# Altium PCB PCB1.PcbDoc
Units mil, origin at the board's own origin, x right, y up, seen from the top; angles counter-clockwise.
Board outline 3797.64 x 3149.61 mil, 2 copper layers (Top Layer, Bottom Layer); 74 components, 106 nets, 398 pads, 67 vias.
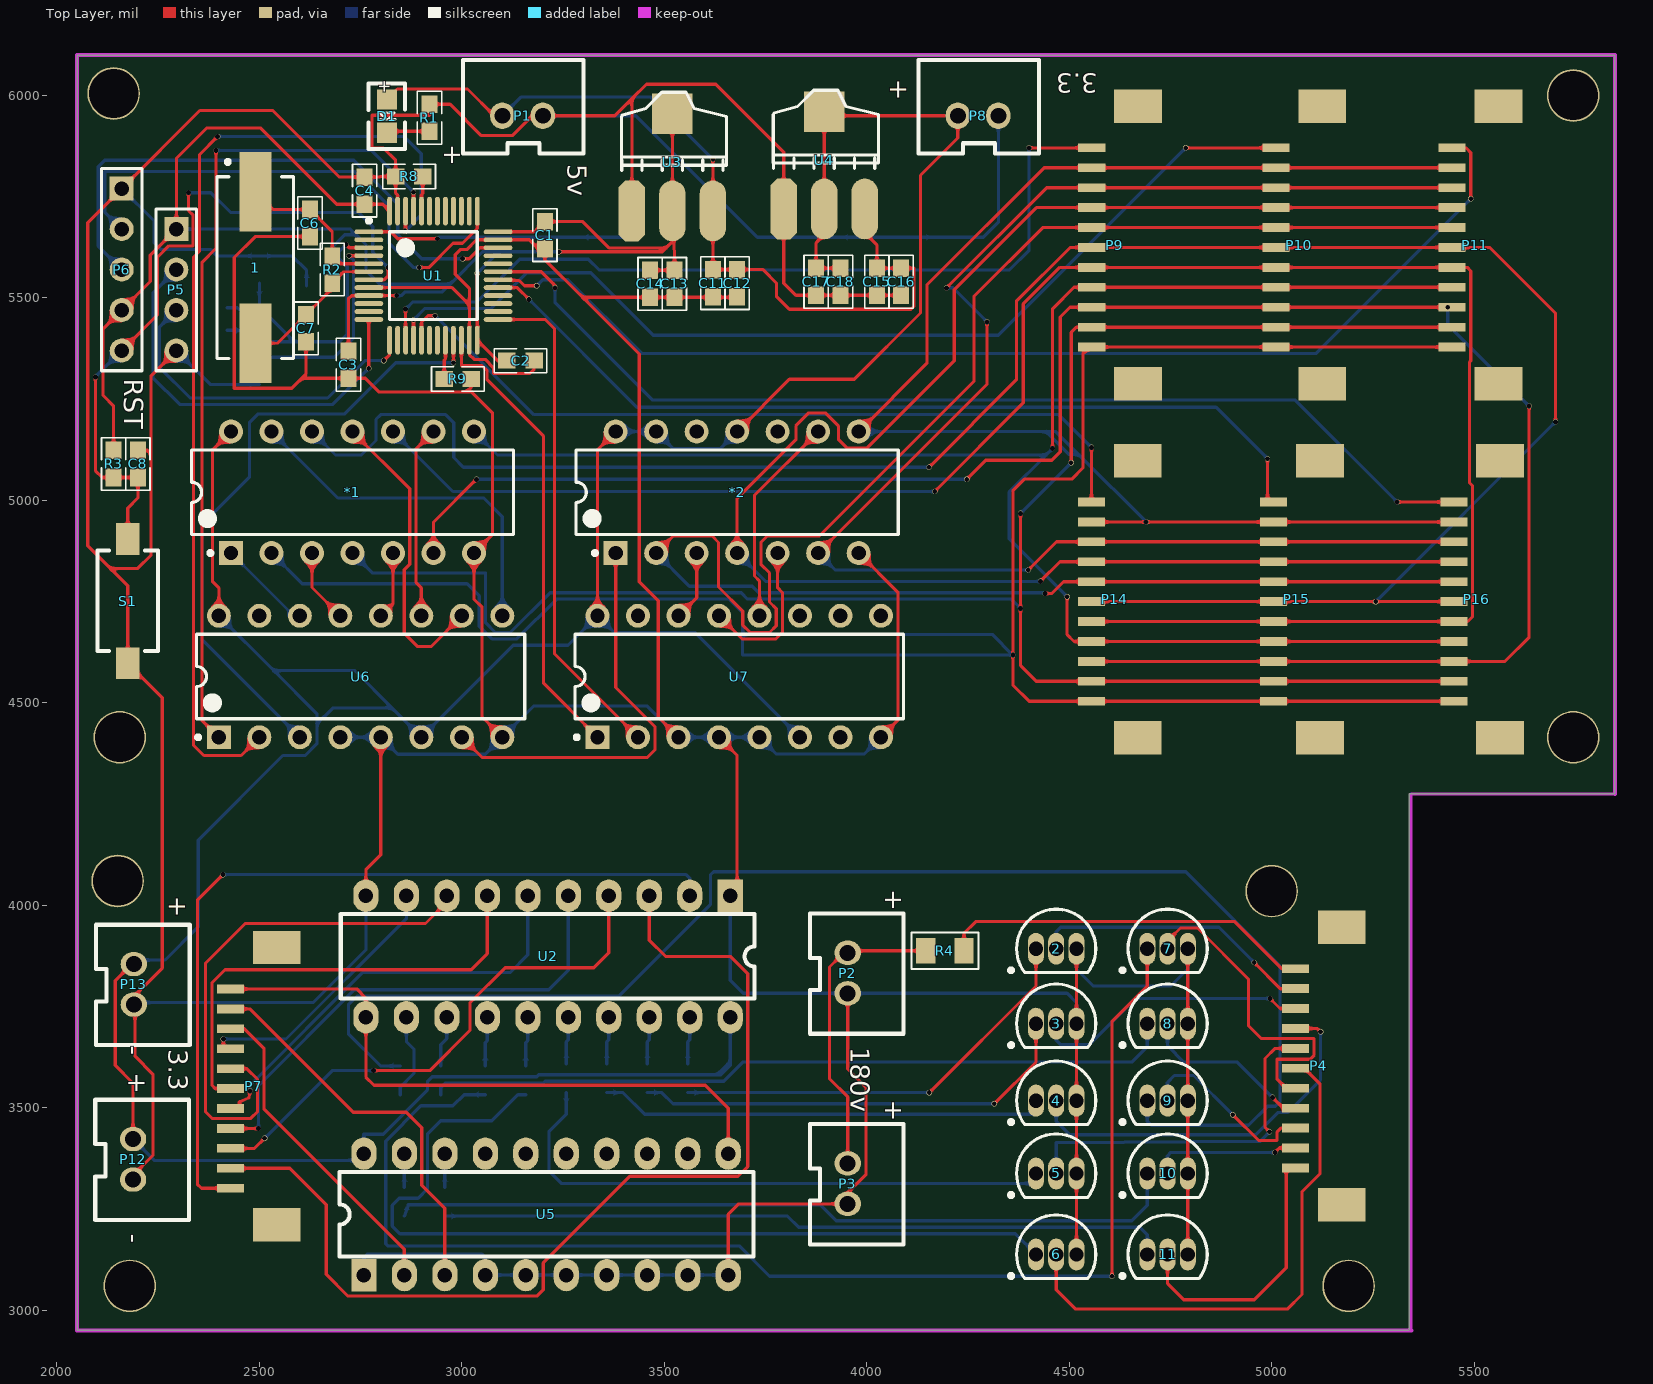
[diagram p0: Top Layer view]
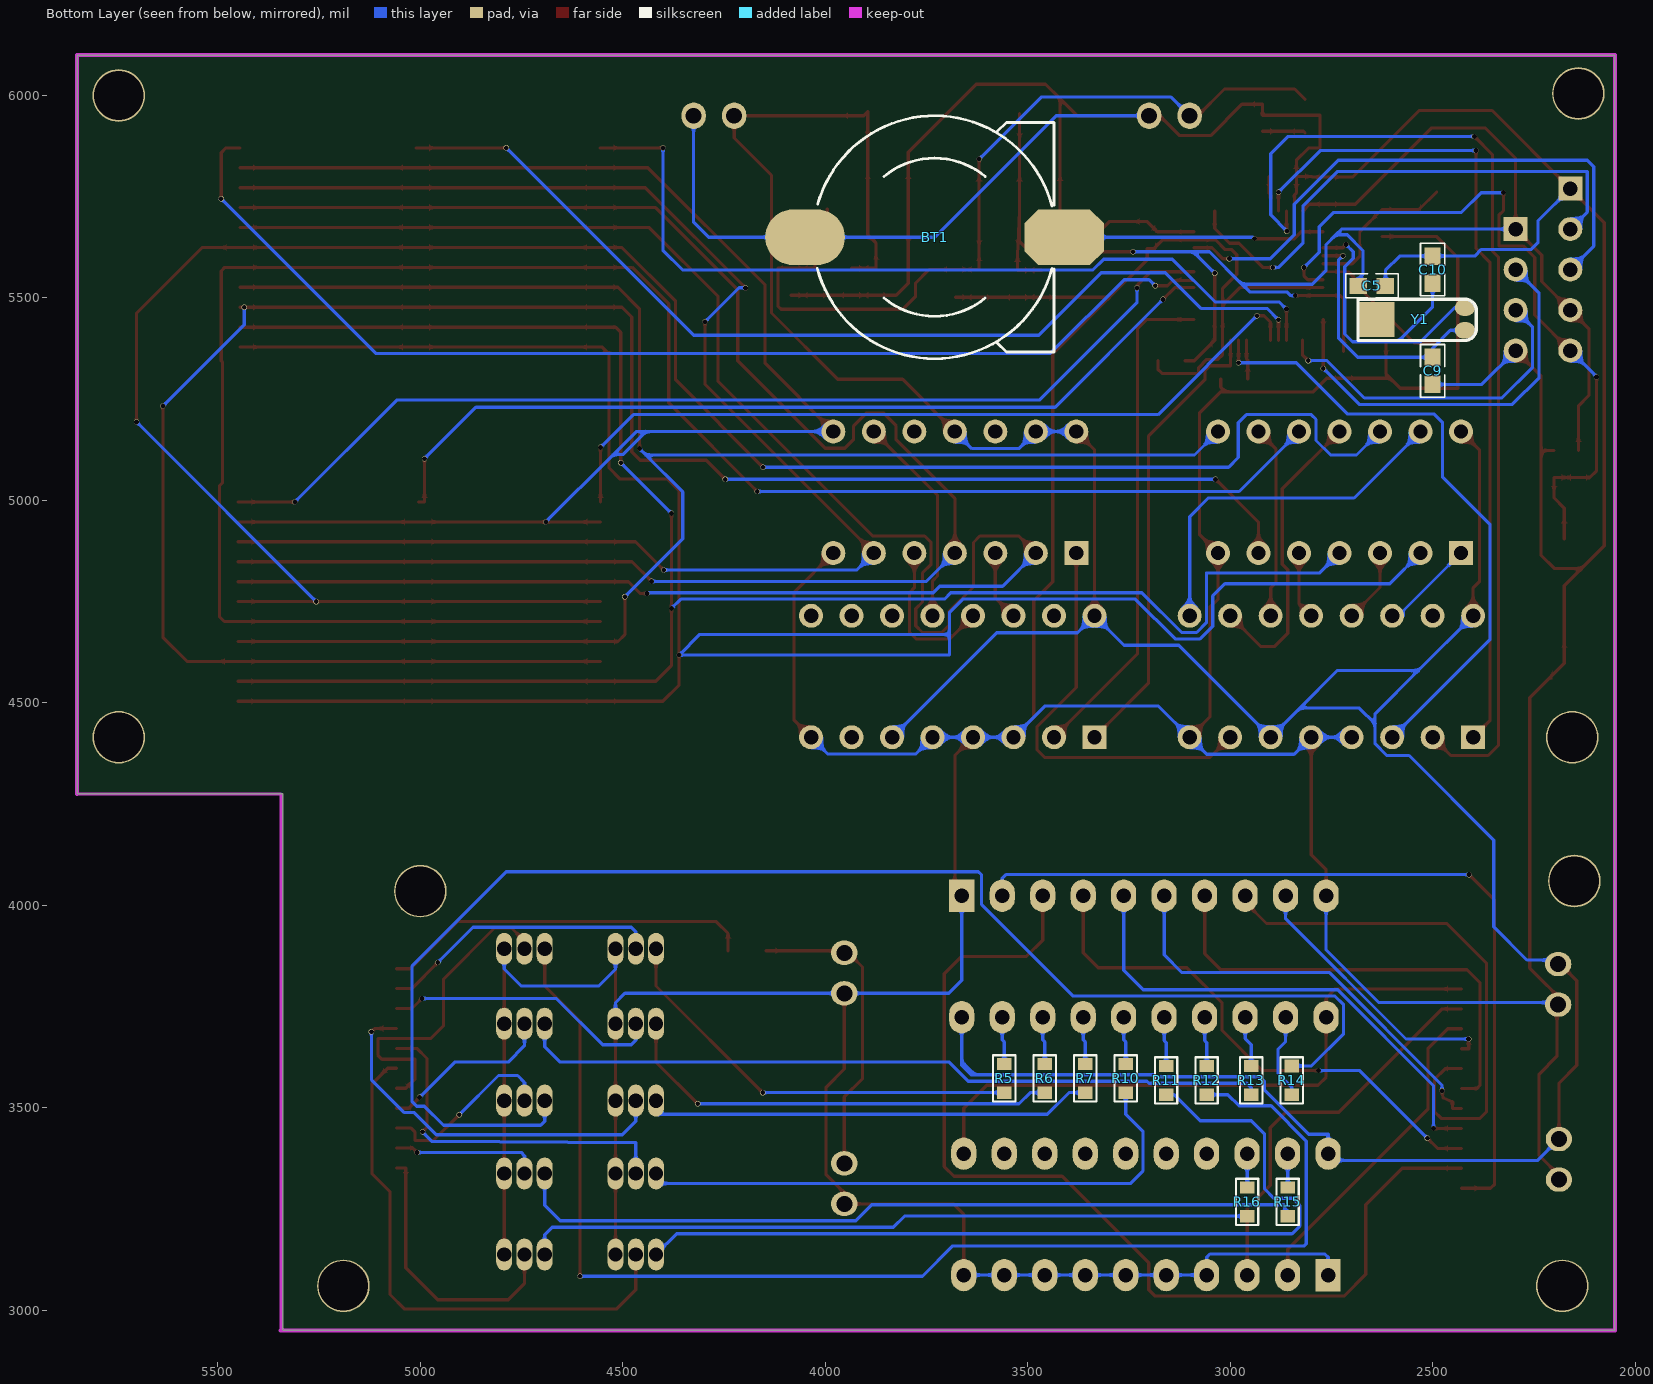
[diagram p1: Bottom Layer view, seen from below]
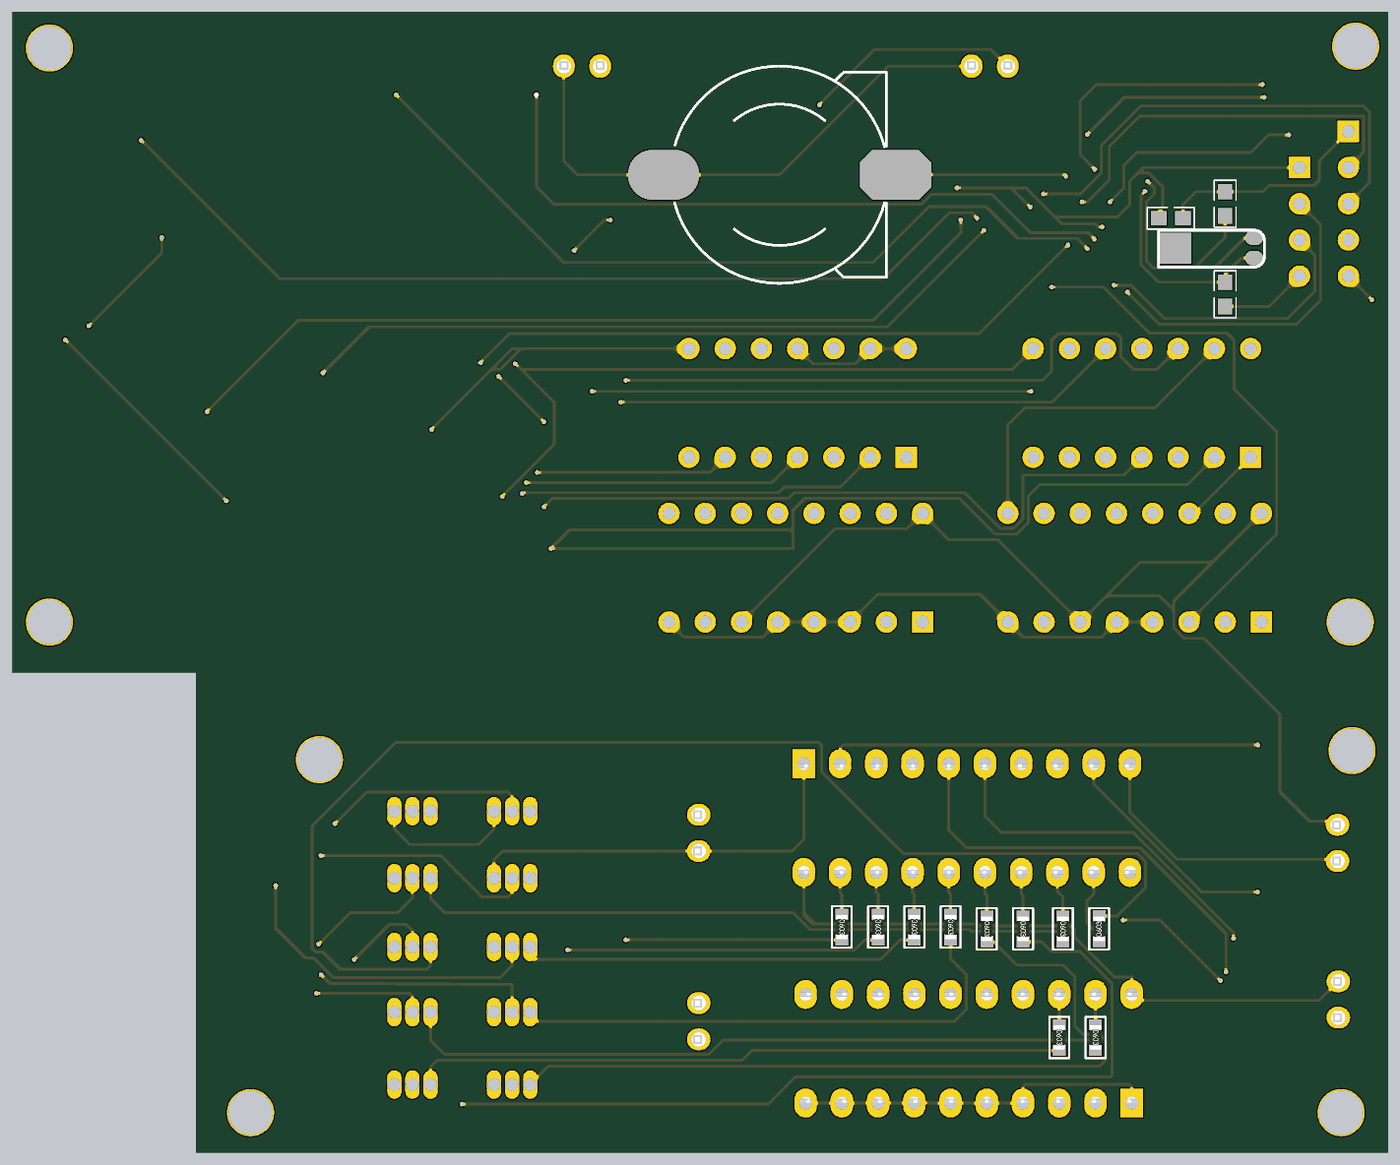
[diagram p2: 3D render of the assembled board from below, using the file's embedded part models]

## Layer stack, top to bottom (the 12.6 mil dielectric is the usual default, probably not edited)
Top Solder: solder mask 0.4, Solder Resist, Dk 3.5
Top Layer: signal copper 1.4
Dielectric 1: dielectric 12.6, FR-4, Dk 4.8
Bottom Layer: signal copper 1.4
Bottom Solder: solder mask 0.4, Solder Resist, Dk 3.5

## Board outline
2050,2950 2050,6099.61 5847.64,6099.61 5847.64,4275 5340,4275 5340,2950

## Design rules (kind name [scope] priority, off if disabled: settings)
Clearance [All] p1: gap=7.87
PolygonConnect [All] p1: connectstyle=Relief reliefconductorwidth=10 reliefentries=4 polygonreliefangle="90 Angle" airgapwidth=10
RoutingVias [All] p1: holewidth=12 width=13 viastyle="Through Hole" minholewidth=12 minwidth=12 maxholewidth=28 maxwidth=50
SolderMaskExpansion [All] p1: expansion=4
Width [All] p1: maxlimit=200 minlimit=7 preferedwidth=7.87
30 further rules are at their usual default settings.

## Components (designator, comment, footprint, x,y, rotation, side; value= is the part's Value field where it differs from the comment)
1 "XTAL" 49S-SMD 2490,5575 r270 top
2 "13001" TO-92A 4468,3892.72 r270 top
3 "13001" TO-92A 4468,3707.72 r270 top
4 "13001" TO-92A 4468,3517.72 r270 top
5 "13001" TO-92A 4468,3337.72 r270 top
6 "13001" TO-92A 4468,3137.72 r270 top
7 "13001" TO-92A 4743,3892.72 r270 top
8 "13001" TO-92A 4743,3707.72 r270 top
9 "13001" TO-92A 4743,3517.72 r270 top
10 "13001" TO-92A 4743,3337.72 r270 top
11 "13001" TO-92A 4743,3137.72 r270 top
*1 "74hc04" DIP-14 2730,5020 r90 top
*2 "74hc04" DIP-14 3680,5020 r90 top
BT1 "Battery" CR1220 3730,5650 r90 bottom
C1 "Cap" 0603-1 3205,5655 r270 top
C2 "Cap" 0603-1 3145,5345 r0 top
C3 "Cap" 0603-1 2720,5335 r270 top
C4 "Cap" 0603-1 2760,5765 r90 top
C5 "Cap" 0603-1 2650,5530 r180 bottom
C6 "" 0603-1 2625,5685 r90 top
C7 "" 0603-1 2615,5425 r270 top
C8 "Cap" 0603-1 2200,5090 r270 top
C9 "" 0603-1 2500,5320 r90 bottom
C10 "" 0603-1 2500,5570 r90 bottom
C11 "Cap" 0603-1 3620,5536.54 r90 top
C12 "Cap" 0603-1 3680,5536.54 r90 top
C13 "Cap" 0603-1 3525,5535 r90 top
C14 "Cap" 0603-1 3465,5535 r90 top
C15 "Cap" 0603-1 4025,5540 r90 top
C16 "Cap" 0603-1 4085,5540 r90 top
C17 "Cap" 0603-1 3875,5540 r90 top
C18 "Cap" 0603-1 3935,5540 r90 top
D1 "LED0" LED0805 2815,5990 r270 top
P1 "5V_in" XH2.54-2 3100,5950 r180 top
P2 "180v_in" XH2.54-2 3953,3882.72 r90 top
P3 "180V_OUT" XH2.54-2 3953,3362.72 r90 top
P4 "Header 11" SMT11P 5173,3262.72 r90 top
P5 "Header 4" HDR1X4 2295,5670 r270 top
P6 "Header 5" HDR1X5 2160,5770 r270 top
P7 "Header 11" SMT11P 2543,3212.72 r90 top
P8 "3.3V_out" XH2.54-2 4225,5950 r180 top
P9 "Header 11" SMT11P 4670,5290 r90 top
P10 "Header 11" SMT11P 5125,5290 r90 top
P11 "Header 11" SMT11P 5560,5290 r90 top
P12 "3.3V_IN" XH2.54-2 2188,3422.72 r90 top
P13 "3.3V_OUT" XH2.54-2 2190,3855 r90 top
P14 "Header 11" SMT11P 4669.17,4415.35 r90 top
P15 "Header 11" SMT11P 5119.17,4415.35 r90 top
P16 "Header 11" SMT11P 5564.17,4415.35 r90 top
R1 "Res1" 0603-1 2920,5945 r270 top
R2 "" 0603-1 2680,5570 r90 top
R3 "Res1" 0603-1 2140,5090 r90 top
R4 "Res1" 0805-1R 4193,3887.72 r180 top
R5 "Res1" 0603R 3558,3572.72 r270 bottom
R6 "Res1" 0603R 3458,3572.72 r270 bottom
R7 "Res1" 0603R 3358,3572.72 r270 bottom
R8 "Res1" 0603-1 2870,5800 r180 top
R9 "Res1" 0603-1 2990,5300 r180 top
R10 "Res1" 0603R 3258,3572.72 r270 bottom
R11 "Res1" 0603R 3158,3567.72 r270 bottom
R12 "Res1" 0603R 3058,3567.72 r270 bottom
R13 "Res1" 0603R 2948,3567.72 r270 bottom
R14 "Res1" 0603R 2848,3567.72 r90 bottom
R15 "Res1" 0603R 2858,3267.72 r270 bottom
R16 "Res1" 0603R 2958,3267.72 r270 bottom
S1 "SW-PB" KEY-SMD1 2175,4905 r270 top
U1 "STM32F103C8T6" LQFP48_N 2930,5555 r0 top
U2 "74ACT573T" DIP-20 3273,3882.72 r270 top
U3 "AMS1117-3.3" AMS1117 3420,5715 r0 top
U4 "AMS1117-3.3" AMS1117 3795,5720 r0 top
U5 "74ACT573T" DIP-20 3148,3227.72 r90 top
U6 "74HC138" DIP-16 2750,4565 r90 top
U7 "74HC138" DIP-16 3685,4565 r90 top
Y1 "32.768K" XTAL32 2420,5420 r0 bottom

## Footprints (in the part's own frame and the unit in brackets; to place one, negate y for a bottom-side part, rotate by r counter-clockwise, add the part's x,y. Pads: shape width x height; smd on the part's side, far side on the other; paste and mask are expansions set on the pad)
49S-SMD [mm]
  rect 5x2 smd: 1(-4.75,0) 2(4.75,0)
  silkscreen extent -6.75,-2.4 5.7,2.4, body extent -6.7,-2.46 6.7,2.44, height 4
0603-1 [mm] "贴片带丝印"
  rect 1.1x1 smd: 1(-0.85,0) 2(0.85,0)
  silkscreen extent -1.65,-0.76 1.65,0.76, body extent -1.14,-0.38 1.14,0.38, height 1
0603R [mm]
  rect 0.762x0.9 smd: 1(-0.9,0)
  rect 0.8x0.9 smd: 2(0.9,0)
  silkscreen extent -1.45,-0.7 1.45,0.7, body extent -0.85,-0.4 0.85,0.4, height 0.56
0805-1R [mm] "small type  ver20150428"
  rect 1.2x1.6 smd: 1(-1.2,0) 2(1.2,0)
  silkscreen extent -2.1,-1.15 2.1,1.15, body extent -1.09,-0.64 1.21,0.7, height 0.76
AMS1117 [mil]
  oct 65x150 smd: 1(0.03,-0.06)
  oval 65x150 smd: 2(100.03,-0.06) 3(200.03,-0.06)
  rect 100x100 smd: 4(100.03,239.94)
  silkscreen extent -26,100 234,293
CR1220 [mm] "钮扣电池"
  oct 3.5x5 smd: 1(0,-8.128)
  oval 3.5x5 smd: 2(0,8.128)
  silkscreen extent -7.62,-7.5 7.62,7.36
DIP-14 [mm] "DIP; 14 Leads; Row Spacing 7.62 mm; Pitch 2.54 mm"
  rect 1.5x1.5 hole 0.9: 1(-3.81,7.62)
  round 1.5 hole 0.9: 2(-3.81,5.08) 3(-3.81,2.54) 4(-3.81,0) 5(-3.81,-2.54) 6(-3.81,-5.08) 7(-3.81,-7.62) 8(3.81,-7.62) 9(3.81,-5.08) 10(3.81,-2.54) 11(3.81,0) 12(3.81,2.54) 13(3.81,5.08) 14(3.81,7.62)
  silkscreen extent -3.93,-10.1 2.65,10.1, body extent -3.6,-10.1 3.6,10.1, height 5.08
DIP-16 [mm] "DIP; 16 Leads; Row Spacing 7.62 mm; Pitch 2.54 mm"
  rect 1.5x1.5 hole 0.9: 1(-3.81,8.89)
  round 1.5 hole 0.9: 2(-3.81,6.35) 3(-3.81,3.81) 4(-3.81,1.27) 5(-3.81,-1.27) 6(-3.81,-3.81) 7(-3.81,-6.35) 8(-3.81,-8.89) 9(3.81,-8.89) 10(3.81,-6.35) 11(3.81,-3.81) 12(3.81,-1.27) 13(3.81,1.27) 14(3.81,3.81) 15(3.81,6.35) 16(3.81,8.89)
  silkscreen extent -3.93,-10.3 2.65,10.31, body extent -3.6,-10.28 3.6,10.28, height 5.08
DIP-20 [mil]
  rect 80x62 hole 35.43: 1(-141,390)
  oval 80x62 hole 35.43: 2(-141,290) 3(-141,190) 4(-141,90) 5(-141,-10) 6(-141,-110) 7(-141,-210) 8(-141,-310) 9(-141,-410) 10(-141,-510) 11(159,-510) 12(159,-410) 13(159,-310) 14(159,-210) 15(159,-110) 16(159,-10) 17(159,90) 18(159,190) 19(159,290) 20(159,390)
  silkscreen extent -95,-572 113,450, body extent -141,-566 165,442, height 177
HDR1X4 [mm] "Connector; Header; 4 Position"
  rect 1.5x1.5 hole 0.9: 1(0,0)
  round 1.5 hole 0.9: 2(2.54,0) 3(5.08,0) 4(7.62,0)
  silkscreen extent -1.27,-1.27 8.89,1.27
HDR1X5 [mm] "Connector; Header; 5 Position"
  rect 1.5x1.5 hole 0.9: 1(0,0)
  round 1.5 hole 0.9: 2(2.54,0) 3(5.08,0) 4(7.62,0) 5(10.16,0)
  silkscreen extent -1.27,-1.27 11.43,1.27
KEY-SMD1 [mm]
  rect 2x1.5 smd: 1(0,0) 2(7.8,0)
  silkscreen extent 0.73,-1.9 7.03,1.9, body extent -0.06,-1.94 7.83,1.91, height 2.5
LED0805 [mil] "1/8W"
  rect 50x50 smd: 1(0,0) 2(82.3,0.2)
  silkscreen extent -40,-45 122,45, body extent 2,-25 80,25, height 20
LQFP48_N [mm] "Thin QFP, 48-Leads, Body 7x7mm, Pitch 0.5mm, IPC Medium Density"
  oval 1.8x0.3 smd: 1(-4.05,2.75) 2(-4.05,2.25) 3(-4.05,1.75) 4(-4.05,1.25) 5(-4.05,0.75) 6(-4.05,0.25) 7(-4.05,-0.25) 8(-4.05,-0.75) 9(-4.05,-1.25) 10(-4.05,-1.75) 11(-4.05,-2.25) 12(-4.05,-2.75) 25(4.05,-2.75) 26(4.05,-2.25) 27(4.05,-1.75) 28(4.05,-1.25) 29(4.05,-0.75) 30(4.05,-0.25) 31(4.05,0.25) 32(4.05,0.75) 33(4.05,1.25) 34(4.05,1.75) 35(4.05,2.25) 36(4.05,2.75)
  oval 0.3x1.8 smd: 13(-2.75,-4.05) 14(-2.25,-4.05) 15(-1.75,-4.05) 16(-1.25,-4.05) 17(-0.75,-4.05) 18(-0.25,-4.05) 19(0.25,-4.05) 20(0.75,-4.05) 21(1.25,-4.05) 22(1.75,-4.05) 23(2.25,-4.05) 24(2.75,-4.05) 37(2.75,4.05) 38(2.25,4.05) 39(1.75,4.05) 40(1.25,4.05) 41(0.75,4.05) 42(0.25,4.05) 43(-0.25,4.05) 44(-0.75,4.05) 45(-1.25,4.05) 46(-1.75,4.05) 47(-2.25,4.05) 48(-2.75,4.05)
  silkscreen extent -4.17,-2.75 2.75,3.57, body extent -3.5,-3.5 3.5,3.5, height 1.6
SMT11P [mm]
  rect 2.1x3 smd: 0(-0.05,0) 0(17.35,0)
  rect 0.55x1.7 smd: 1(2.25,2.9) 2(3.5,2.9) 3(4.75,2.9) 4(6,2.9) 5(7.25,2.9) 6(8.5,2.9) 7(9.75,2.9) 8(11,2.9) 9(12.25,2.9) 10(13.5,2.9) 11(14.75,2.9)
TO-92A [mm] "TO, Flat Index; 3 In-Line, Axial Leads; Body Dia. 4.5mm; Leads 0.51 x 0.48 mm (max)"
  oval 2x1 hole 0.9: 1(0,-1.27) 2(0,0) 3(0,1.27)
  silkscreen extent -2.48,-2.95 1.5,2.48, body extent -2.5,-2.5 1.5,2.5, height 6.86
XH2.54-2 [mil]
  oval 60x65 hole 39.37: 1(0,0) 2(-100.1,0)
  silkscreen extent -200,-138 97,93, body extent -198,-142 98,94, height 276
XTAL32 [mil]
  oval 50x40 smd: 1(0,0) 2(0,-56)
  rect 92.13x86 smd: ""(220,-27)
  silkscreen extent -28,-77 264,25

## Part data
1: "Crystal Oscillator"
2 3 4 5 6 7 8 9 10 11: "NPN三极管"
*1 *2: "非门"
BT1: "备份电池"
C1 C2 C3 C4 C5 C8 C11 C12 C13 C14 C15 C16 C17 C18: "Capacitor"
C6 C7 C9 C10: library part Cap, "Capacitor"
D1: "Typical INFRARED GaAs LED"
P1 P2 P3 P8 P12 P13: library part "Header 2", "Header, 2-Pin"
P4 P7 P9 P10 P11 P14 P15 P16: "Header, 11-Pin"
P5: "Header, 4-Pin"
P6: "Header, 5-Pin"
R1 R3 R4 R5 R6 R7 R8 R9 R10 R11 R12 R13 R14 R15 R16: "Resistor"
R2: library part Res2, "Resistor"
S1: "Switch"
U1: "STM32 ARM-based 32-bit MCU with 64 Kbytes Flash, 48-pin LQFP, Industrial Temperature"
U2 U5: "双向数据传输"
U3 U4: library part AMS1117
U6 U7: "138译码器"
Y1: library part XTAL_1, "Crystal Oscillator"

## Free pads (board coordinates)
  round 129.92 hole 122.05: 0(2140,6005) 1(5745,4415) 2(2155,4415) 3(5745,6000) 4(2180,3060) 5(2150,4060) 6(5190,3060) 7(5000,4035)

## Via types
v1: diameter 13, hole 12, Top Layer to Bottom Layer, 63 vias
v2: diameter 12, hole 12, Top Layer to Bottom Layer, 4 vias

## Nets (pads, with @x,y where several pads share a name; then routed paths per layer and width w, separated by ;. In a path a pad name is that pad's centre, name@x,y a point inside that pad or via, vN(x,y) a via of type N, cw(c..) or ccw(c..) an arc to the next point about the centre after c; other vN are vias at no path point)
BOOT0: R8.1 U1.44 | length 86.8
  Top Layer w7.87: U1.44 2900.47,5755 2903.46,5757.99 R8.1
BOOT1: R9.2 U1.20 | length 96.8
  Top Layer w7.87: R9.2 2956.54,5346 2959.53,5348.99 U1.20
C1_1: 2.2 P4.10 | length 700.1
  Top Layer w7.87: v1(4957,3858.72) 5021.5,3794.21 P4.10
  Bottom Layer w7.87: 2.2 4468,3934.72 4479,3945.72 4870,3945.72 v1(4957,3858.72)
C1_2: 3.2 P4.9 | length 693.8
  Top Layer w7.87: v1(4996,3769.72) 5020.72,3745 P4.9
  Bottom Layer w7.87: 3.2 4468,3666.72 4479,3655.72 4550,3655.72 4664,3769.72 v1(4996,3769.72)
C1_3: 4.2 P4.8 | length 958.1
  Top Layer w7.87: P4.8 5112.93,3695.79 v1(5121,3687.71)
  Bottom Layer w7.87: 4.2 4468,3466.72 4501.5,3433.22 4960.5,3433.22 5015.23,3487.95 5039.48,3487.95 5121,3569.47 v1(5121,3687.71)
C1_4: 5.2 P4.7 | length 883.8
  Top Layer w7.87: v1(4995,3440.72) 4983.63,3452.08 4983.63,3621.58 5008.63,3646.57 P4.7
  Bottom Layer w7.87: 5.2 4468,3413.72 4971.75,3417.47 v1(4995,3440.72)
C1_5: 6.2 P4.6 | length 1344.3
  Top Layer w7.87: 6.2 4468,3050.72 4516,3002.72 5039,3002.72 5075,3038.72 5075,3292.72 5119.85,3337.57 5119.85,3558.51 5081,3597.36 P4.6
C1_6: 7.2 P4.5 | length 815.2
  Top Layer w7.87: 7.2 4743,3911.9 4775,3943.9 4816.82,3943.9 4943,3817.72 4943,3702.72 4975,3670.72 5105,3670.72 5105,3630 5095,3620 5013.55,3620 5013.55,3570.6 5036,3548.15 P4.5
C1_7: 8.2 P4.4 | length 434.5
  Top Layer w7.87: v1(5002,3525.72) 5028.78,3498.94 P4.4
  Bottom Layer w7.87: 8.2 4743,3652.72 4783,3612.72 4915,3612.72 v1(5002,3525.72)
C1_8: 9.2 P4.3 | length 459.6
  Top Layer w7.87: v1(4904,3482.72) 4967.71,3419 5013.55,3419 5013.55,3440.27 5023,3449.72 P4.3
  Bottom Layer w7.87: 9.2 4743,3562.72 4760,3579.72 4807,3579.72 v1(4904,3482.72)
C1_9: 10.2 P4.2 | length 367.6
  Top Layer w7.87: v1(5008,3389.72) 5018.8,3400.51 P4.2
  Bottom Layer w7.87: 10.2 4743,3381.72 4751,3389.72 v1(5008,3389.72)
C1_10: 11.2 P4.1 | length 683.7
  Top Layer w7.87: 11.2 4743,3065.72 4783,3025.72 4957,3025.72 5036,3104.72 5036,3351.3 P4.1
D1_1: R5.1 U2.19 | length 117.6
  Bottom Layer w7.87: R5.1 3558,3662.72 3563,3667.72 U2.19
D1_2: R6.1 U2.18 | length 117.6
  Bottom Layer w7.87: R6.1 3458,3662.72 3463,3667.72 U2.18
D1_3: R7.1 U2.17 | length 117.6
  Bottom Layer w7.87: R7.1 3358,3662.72 3363,3667.72 U2.17
D1_4: R10.1 U2.16 | length 117.6
  Bottom Layer w7.87: R10.1 3258,3662.72 3263,3667.72 U2.16
D1_5: R11.1 U2.15 | length 122.6
  Bottom Layer w7.87: R11.1 3158,3660.72 3163,3665.72 U2.15
D1_6: R12.1 U2.14 | length 122.6
  Bottom Layer w7.87: R12.1 3058,3660.72 3063,3665.72 U2.14
D1_7: R13.1 U2.13 | length 126.8
  Bottom Layer w7.87: R13.1 2948,3655.72 2963,3670.72 U2.13
D1_8: R14.1 U2.12 | length 213.4
  Bottom Layer w7.87: R14.1 2848,3550.72 2882,3584.72 2882,3644.72 2863,3663.72 U2.12
D1_9: R15.1 U5.19 | length 83.6
  Bottom Layer w7.87: R15.1 U5.19
D1_10: R16.1 U5.18 | length 83.6
  Bottom Layer w7.87: R16.1 U5.18
GND: 2.3 3.3 4.3 5.3 6.3 7.3 8.3 9.3 10.3 11.3 *1.7 *2.7 BT1.2 C1.2 C2.2 C3.2 C4.2 C5.2 C6.1 C7.2 C8.1 C9.1 C10.2 C11.1 C12.1 C13.1 C14.1 C15.1 C16.1 C17.1 C18.1 P1.2 P2.2 P3.2 P5.4 P6.1 P8.2 P12.2 P13.2 R1.1 R8.2 R9.1 S1.2 U1.8 U1.23 U1.35 U1.47 U2.1 U2.10 U3.1 U4.1 U5.1 U5.4 U5.5 U5.6 U5.7 U5.8 U5.9 U5.10 U6.4 U6.5 U6.8 U7.3 U7.4 U7.5 U7.8 | length 22436.1
  Top Layer w7.87: P12.2 2188,3333 2237,3382 2237,3582.72 2193,3626.72 2193,3754.9 2169.9,3754.9 2260,3845 2260,4512.91 S1.2 2175,4789 2132,4832 ; C8.1 2224,5123.46 2232,5115.46 ; P5.4 2232,5307 2232,5115.46 ; C7.2 2615,5312 2604.54,5301.54 ; C6.1 2489.54,5651.54 2438,5600 2438,5277 2580,5277 2604.54,5301.54 ; U2.10 2763,4088 2800,4125 U6.5 ; U1.8 2976,5525.47 3018.58,5482.89 ; U1.47 2841.42,5754 2836.54,5758.88 R8.2 ; R9.1 3023.46,5280 3011.46,5268 ; U6.8 3050,4465 3050,4736 3030,4756 *1.7 3076,4916 3076,5215.46 3023.46,5268 3011.46,5268 ; C2.2 3178.46,5323.97 3168,5313.5 3078.07,5313.5 3078.07,5328 3057.76,5348.31 3030.28,5348.31 3018.58,5360 U1.23 3018.58,5482.89 ; U3.1 3420.03,5992.03 ; U7.3 3485,4465 3485,4752 3438,4799 3438,5361.47 3297.93,5501.54 ; U7.4 3680,4370 U2.1@3680,4035 ; U5.10 3658,3236.72 3683.9,3262.62 P3.2 3953,3289.72 3998,3334.72 3998,3550.72 3953,3595.72 P2.2 ; C12.1@3678.47,5501.54 C13.1 C14.1 3297.93,5501.54 ; *2.7 4077,4773 4077,4457 U7.8 ; C16.1 C15.1 C18.1 C17.1 3825,5506.54 3795.03,5536.5 U4.1 3795.03,5860 3627.03,6028 3456,6028 3420.03,5992.03 ; 6.3 5.3 4.3 3.3 2.3 ; 11.3 10.3 9.3 8.3 7.3 ; 2132,4832 2076,4888 2076,5686 P6.1 2353,5963 2533.46,5963 2698,5798.46 C4.2 2797,5798.46 2798.54,5800 R8.2 ; 2132,4832 2200,4832 2232,4864 2232,5115.46 ; 2604.54,5301.54 C3.2 2761.46,5301.54 2795,5268 3011.46,5268 ; R8.2 2836.54,5840 2806.54,5870 2778,5870 2778,5951 2920,5951 R1.1 2971,5978.46 3048.46,5901 3125,5901 3174,5950 P1.2 3378,5950 3420.03,5992.03 ; 3018.58,5482.89 3018.58,5523.69 2983.69,5558.59 2983.69,5607 2995.95,5619.27 3011.95,5619.27 3036.27,5643.58 U1.35 3166.95,5643.58 3189,5621.54 C1.2 3205,5594.47 3297.93,5501.54
  Bottom Layer w7.87: P6.1 2240,5690 2240,5636 2256,5620 2379.46,5620 2396,5603.46 C10.2 2581.07,5603.46 2616.54,5568 C5.2 ; P13.2@2193,3760 2633.28,3760 2763,3889.72 U2.10 ; P5.4 2378.46,5286.54 C9.1 ; U6.4 U6.5 2842,4373 3058,4373 U6.8 3177,4492 3458,4492 U7.3 U7.4 U7.5 3776.34,4373.66 3993.66,4373.66 U7.8 ; U5.1 2758,3130.72 2766,3138.72 3050,3138.72 3058,3130.72 U5.4 U5.5 U5.6 U5.7 U5.8 U5.9 U5.10 ; P1.2 3430,5950 3730,5650 BT1.2 4288,5650 4325.1,5687.1 P8.2 ; U2.1 3663,3814.62 3695,3782.62 P2.2 4495,3782.62 4518,3759.62 3.3 ; 2.3 4518,3841.72 4559,3800.72 4751,3800.72 4793,3842.72 7.3
LE: P7.11 U2.11 U5.11 | length 1577.5
  Top Layer w7.87: P7.11 2740.29,3793.42 2763,3770.72 U2.11 2763,3575.72 2783,3555.72 3601,3555.72 3658,3498.72 U5.11
Net2_1: 2.1 R5.2 | length 1061.1
  Top Layer w7.87: v1(4154.57,3537.28) 4418,3800.72 2.1
  Bottom Layer w7.87: R5.2 v1(4154.57,3537.28)
Net3_1: 3.1 R6.2 | length 1109.1
  Top Layer w7.87: v1(4315,3509.72) 4418,3612.72 3.1
  Bottom Layer w7.87: R6.2 3494,3537.28 3521.57,3509.72 v1(4315,3509.72)
Net4_1: 4.1 R7.2 | length 1116.2
  Bottom Layer w7.87: R7.2 3398,3537.28 3451.57,3483.72 4418,3483.72 4.1
Net5_1: 5.1 R10.2 | length 1451.6
  Bottom Layer w7.87: R10.2 3258,3483.72 3215,3440.72 3215,3344.72 3247,3312.72 4418,3312.72 5.1
Net6_1: 6.1 R11.2 | length 2192.6
  Bottom Layer w7.87: R11.2 3138.57,3532.28 3074.08,3467.79 2948.15,3467.79 2915.08,3434.72 2915.08,3299.41 2892,3276.34 2845.62,3276.34 2828,3258.72 2828,3207.72 2847,3188.72 4367,3188.72 6.1
Net7_1: 7.1 R12.2 | length 3219.6
  Top Layer w7.87: v1(4606,3083.72) 4606,3713.72 4693,3800.72 7.1
  Bottom Layer w7.87: R12.2 3005.56,3532.28 2978,3504.72 2899,3504.72 2812,3417.72 2812,3163.72 2817,3158.72 3685,3158.72 3760,3083.72 v1(4606,3083.72)
Net8_1: 8.1 R13.2 | length 1861.2
  Bottom Layer w7.87: R13.2 2948,3549.59 2959,3560.59 3200.56,3560.59 3205.56,3565.59 3646.75,3565.59 3693.87,3612.72 4655,3612.72 4693,3650.72 8.1
Net9_1: 9.1 R14.2 | length 3550.3
  Bottom Layer w7.87: R14.2 2799.62,3603.15 2720,3682.77 2720,3754.72 2741,3775.72 3388,3775.72 3614,4001.72 3614,4074.72 3622,4082.72 4788,4082.72 5020.31,3850.4 5020.31,3514.72 5009.29,3503.7 4989.98,3503.7 4943,3456.72 4703,3456.72 4693,3466.72 9.1
Net10_1: 10.1 R15.2 | length 1966.2
  Bottom Layer w7.87: R15.2 2867.87,3260.59 3885.13,3260.59 3924.91,3220.8 4655,3220.8 4693,3258.8 10.1
Net11_1: 11.1 R16.2 | length 1802.9
  Bottom Layer w7.87: R16.2 3804.43,3232.28 3831.66,3205.06 4674.66,3205.06 4693,3186.72 11.1
NetBT1_1: BT1.1 U1.1 | length 648
  Top Layer w7.87: U1.1 2824.71,5663.27 2841.65,5646.33 v2(2939.98,5646.33)
  Bottom Layer w7.87: v2(2939.98,5646.33) 2943.66,5650 BT1.1
NetC9_2: C9.2 U1.4 Y1.1 | length 629.8
  Top Layer w7.87: v1(2721.54,5604.21) U1.4
  Bottom Layer w7.87: Y1.1 2456,5420 2500,5376 C9.2 2684.84,5353.46 2732.68,5401.3 2732.68,5593.08 v1(2721.54,5604.21)
NetC10_1: C10.1 U1.3 Y1.2 | length 816.7
  Top Layer w7.87: v1(2713.9,5631.9) 2721.9,5623.9 U1.3
  Bottom Layer w7.87: Y1.2 2446,5476 2530,5392 2586,5392 ; C10.1 2500,5478 2586,5392 ; v1(2713.9,5631.9) 2696,5614 2696,5598 2716.93,5577.07 2716.93,5410.93 2698,5392 2586,5392
NetD1_2: D1.2 R1.2 | length 106.4
  Top Layer w7.87: D1.2 2819.04,5911.54 R1.2
NetP4_11: P4.11 R4.1 | length 921.7
  Top Layer w7.87: R4.1 4240.24,3930.72 4269.18,3959.65 4909.07,3959.65 5025.29,3843.42 P4.11
NetP7_1: P7.1 U2.2 | length 2076.2
  Top Layer w7.87: v1(2410,4075.72) 2347,4012.72 2347,3311.3 2357,3301.3 P7.1
  Bottom Layer w7.87: v1(2410,4075.72) 3554,4075.72 3563,4066.72 U2.2
NetP7_2: P7.2 U2.3 | length 2543.3
  Top Layer w7.87: P7.2 2575.2,3350.51 2665,3260.72 2665,3088.72 2719,3034.72 3185,3034.72 3201,3050.72 3201,3116.72 3415,3330.72 3682,3330.72 3706,3354.72 3706,3830.72 3663,3873.72 3503,3873.72 3463,3913.72 U2.3
NetP7_3: P7.3 U2.4 | length 1315.1
  Top Layer w7.87: P7.3 2488.01,3399.72 v1(2513,3424.72) ; v1(2782,3591.72) 2921,3591.72 3020,3690.72 3020,3758.72 3107,3845.72 3326,3845.72 3363,3882.72 U2.4
  Bottom Layer w7.87: v1(2513,3424.72) 2680,3591.72 v1(2782,3591.72)
NetP7_4: P7.4 U2.5 | length 1242.3
  Top Layer w7.87: P7.4 v1(2498.01,3448.94)
  Bottom Layer w7.87: v1(2498.01,3448.94) 2498.01,3555 2734.48,3791.46 3215,3791.46 3263,3839.46 U2.5
NetP7_5: P7.5 U2.6 | length 1060.8
  Top Layer w7.87: P7.5 2451,3498.15 2451,3514.72 2474.1,3524.72 v1(2477,3541.72)
  Bottom Layer w7.87: v1(2477,3541.72) 2477,3556.26 2754.46,3833.72 3119,3833.72 3163,3877.72 U2.6
NetP7_6: P7.6 U2.7 | length 1155.3
  Top Layer w7.87: P7.6 2391,3547.36 2383,3555.36 2383,3808.72 2415,3840.72 3023,3840.72 3063,3880.72 U2.7
NetP7_7: P7.7 U2.8 | length 1340.9
  Top Layer w7.87: P7.7 2468.74,3596.57 2495.31,3570 2495.31,3490.03 2479,3473.72 2383,3473.72 2367,3489.72 2367,3857 2465,3955 2910.28,3955 2963,4007.72 U2.8
NetP7_8: P7.8 U2.9 | length 673.7
  Top Layer w7.87: v1(2411,3669.72) 2411,3645.79 P7.8
  Bottom Layer w7.87: v1(2411,3669.72) 2565.8,3669.72 2863,3966.92 U2.9
NetP7_9: P7.9 U5.2 | length 806.1
  Top Layer w7.87: P7.9 2463,3695 2511.06,3646.94 2511.06,3497.66 2858,3150.72 U5.2
NetP7_10: P7.10 U5.3 | length 981.4
  Top Layer w7.87: P7.10 2476.5,3744.21 2732,3488.72 2863,3488.72 2901,3450.72 2901,3308.72 2958,3251.72 U5.3
PA0: U1.10
PA1: U1.11
PA2: P5.2 U1.12 | length 1009.5
  Top Layer w7.87: v1(2770,5326) 2770,5446.73 U1.12
  Bottom Layer w7.87: P5.2 2237,5512 2237,5303 2303,5237 2681,5237 v1(2770,5326)
PA3: P5.3 U1.13 | length 838.6
  Top Layer w7.87: v1(2807.21,5345.21) 2821.73,5359.73 U1.13
  Bottom Layer w7.87: P5.3 2253,5428 2253,5329 2329,5253 2668.62,5253 2760.83,5345.21 v1(2807.21,5345.21)
PA4: U1.14
PA5: P9.11 U1.15 | length 2106.6
  Top Layer w7.87: U1.15 v1(2861.1,5472.41) ; v1(4401,5870.71) P9.11
  Bottom Layer w7.87: v1(2861.1,5472.41) 2878.75,5490.06 3037.07,5490.06 3142.61,5595.61 3312.47,5595.61 3339.08,5569 4352,5569 4401,5618 v1(4401,5870.71)
PA6: P10.11 U1.16 | length 2484
  Top Layer w7.87: U1.16 v1(2880.79,5446) ; v1(4788,5870.71) P10.11
  Bottom Layer w7.87: v1(2880.79,5446) 2909.1,5474.31 3072.31,5474.31 3160,5562 3318.5,5562 3472.5,5408 4325.29,5408 v1(4788,5870.71)
PA7: P14.11 U1.17 | length 1975.2
  Top Layer w7.87: U1.17 2900.47,5440 2916.47,5456 v1(2934,5456) ; P14.11 v1(4555,5131)
  Bottom Layer w7.87: v1(2934,5456) 3178,5212 4474,5212 v1(4555,5131)
PA8: P15.11 U1.29 | length 2197.5
  Top Layer w7.87: U1.29 3137,5525.47 v1(3166,5496.47) ; v1(4990,5103) 4990,4996.06 P15.11
  Bottom Layer w7.87: v1(3166,5496.47) 3432.47,5230 4863,5230 v1(4990,5103)
PA9: P11.11 U1.30 | length 2810.9
  Top Layer w7.87: U1.30@3091.42,5543.19 3141.55,5543.19 3154.74,5530 v1(3185,5530) ; P11.11 5480,5870.71 5492,5858.71 v1(5492,5745)
  Bottom Layer w7.87: v1(3185,5530) 3200.16,5545.16 3262.09,5545.16 3444.25,5363 5110,5363 v1(5492,5745)
PA10: P16.11 U1.31 | length 2614.4
  Top Layer w7.87: U1.31 3196.34,5564.84 v1@3230,5531.18 ; v1(5309.94,4996.06) P16.11
  Bottom Layer w7.87: v1(3230,5525) 3230,5489.5 3471.72,5247.79 5058.21,5247.79 v1(5309.94,4996.06)
PA11: U1.32
PA12: U1.33
PB0: U1.18
PB1: U1.19
PB3: U1.39
PB4: U1.40
PB5: U1.41
PB6: U1.42
PB7: U1.43
PB8: U1.45 U6.1 | length 2058
  Top Layer w7.87: v1(2393,5864) 2393,5622.33 2358,5587.33 2358,4457 U6.1 ; U1.45 v1(2880.79,5761.21)
  Bottom Layer w7.87: v1(2393,5864) 2778,5864 v1(2880.79,5761.21)
PB9: U1.46 U6.2 | length 2498.5
  Top Layer w7.87: v1(2397,5899) 2352.09,5854.09 2352.09,5615.09 2337,5600 2337,4396 2363,4370 2455,4370 U6.2 ; v1(2860,5665) 2861.1,5666.1 U1.46
  Bottom Layer w7.87: v1(2397,5899) 2857,5899 2900,5856 2900,5705 v1(2860,5665)
PB10: U1.21 U6.3 | length 1546.8
  Top Layer w7.87: v1(2979.21,5340) U1.21
  Bottom Layer w7.87: U6.3 2358,4657 2358,4940 2476,5058 2476,5193 2496,5213 2710,5213 2837,5340 v1(2979.21,5340)
PB11: U1.22 U7.1 | length 1148.9
  Top Layer w7.87: U1.22 2998.9,5333.67 3000.01,5332.56 3049.76,5332.56 3062.32,5320 3062.32,5297.75 3202,5158.08 3202,4548 U7.1
PB12: U1.25 U7.2 | length 1243.3
  Top Layer w7.87: U1.25 3206.27,5446.73 3229,5424 3229,4621 U7.2
PB13: U1.26
PB14: U1.27
PB15: U1.28
PH0: 1.2 C7.1 R2.1 U1.6 | length 361.5
  Top Layer w7: 1.2 2544.53,5387.99 C7.1 2680,5523.46 R2.1 2708.31,5564.84 U1.6
PH1: 1.1 C6.2 R2.2 U1.5 | length 389.2
  Top Layer w7: 1.1 2533.54,5718.46 C6.2 2680,5663.46 R2.2
  Top Layer w7.87: R2.2 2698.94,5584.53 U1.5
RESET: C8.2 P6.5 R3.1 S1.1 U1.7 | length 1778
  Top Layer w7.87: v1(2095,5305) 2095,5073.54 2112,5056.54 R3.1 C8.2 2200,5006 2175,4981 S1.1 ; P6.5 2248,5458 2248,5600 2276.66,5628.66 2336.34,5628.66 2336.34,5704.42 2325,5715.76 v2(2325,5760) ; U1.7 2808,5545.16 2818,5555.16 v1(2818,5575)
  Bottom Layer w7.87: v1(2095,5305) P6.5 ; v2(2325,5760) 2380,5760 2428.66,5711.34 2744.66,5711.34 2780,5676 2780,5613 v1(2818,5575)
SWDCLK: P6.2 U1.37 | length 1314.3
  Top Layer w7.87: v1(2895,5575) 2918.19,5575 2978.2,5635.01 3001.65,5635.01 3038.27,5671.63 U1.37
  Bottom Layer w7.87: P6.2 2118,5712 2118,5812 2736,5812 2820,5728 2820,5636.48 2881.48,5575 v1(2895,5575)
SWDIO: P6.3 U1.34 | length 1428
  Top Layer w7.87: v1(3002,5597) 3018,5597 3044.9,5623.9 U1.34
  Bottom Layer w7.87: P6.3 2102,5628 2102,5824 2118,5840 2733,5840 2841.65,5731.35 2841.65,5656 2900.65,5597 v1(3002,5597)
VCC-3.3: C1.1 C2.1 C3.1 C4.1 C5.1 C13.2 C14.2 P5.1 P6.4 R3.2 U1.9 U1.24 U1.36 U1.48 U3.2 U3.4 | length 4691.6
  Top Layer w7.87: R3.2 2140,5233 2114,5259 2114,5424 P6.4 2230.55,5540.55 2230.55,5605.55 P5.1 2295,5844.42 2370.58,5920 2502.54,5920 2691,5731.54 C4.1 2804.64,5731.54 U1.48 ; C3.1 2720,5497.79 2728,5505.79 U1.9 v2(2839.21,5505.79) ; v1(3038.27,5561.27) U1.24 3088.82,5345 C2.1 ; U1.36 3179.8,5663.27 C1.1 3299,5688.46 3364.46,5623 3504,5623 ; v1(3240,5614) 3495,5614 3504,5623 ; C14.2 C13.2 3525,5604 U3.2 ; U3.4 U3.2 ; 3504,5623 3520.03,5639.03 U3.2
  Bottom Layer w7.87: P5.1 2725,5670 2739,5656 ; C5.1 2683.46,5547 2672,5558.46 2672,5617 2711,5656 2739,5656 ; v2(2839.21,5505.79) 2850.79,5505.79 2860,5515 2952,5515 2971,5534 ; v1(3038.27,5561.27) 3091,5614 ; v1(3240,5614) 3091,5614 ; 2739,5656 2763,5632 2763,5568 2797,5534 2971,5534 ; 2971,5534 3051,5614 3091,5614
VCC-3.3EX: *1.14 *2.11 *2.13 *2.14 C17.2 C18.2 P8.1 P12.1 P13.1 U2.20 U4.2 U4.4 U5.20 U6.6 U6.16 U7.6 U7.16 | length 8474.8
  Top Layer w7.87: P12.1 2188,3560.72 2144,3604.72 2144,3814 P13.1@2193,3863 ; U6.16 2400,4784 2384,4800 2384,5124 *1.14 ; U7.16 3335,5125 *2.14 ; *2.11 3809,5299 3969,5299 4132.75,5462.75 4132.75,5802.75 4225,5895 P8.1 ; C18.2 C17.2 3875,5636 3895.03,5656.03 U4.2 U4.4 3904.97,5950 4192,5950
  Bottom Layer w7.87: P13.1@2172.64,3867.36 2175,3865 2267.28,3865 2349,3946.72 2349,4161 2558,4370 2613.46,4370 2642,4398.54 2642,4448 ; P12.1 2240,3370.72 2240,3370 2741.28,3370 U5.20 2758,3434.72 2806,3434.72 2915,3543.72 2915,3564.34 2927,3576.34 3185,3576.34 3190,3581.34 3631,3581.34 ; U6.16 2534.98,4580.02 ; *2.14 *2.13 3522,5128 3638,5128 *2.11 ; U2.20 3663,3613.34 ; U7.6 3577,4673 3377,4673 U7.16 3262.16,4642.16 3127.16,4642.16 U6.6 2827.96,4487.04 ; 2534.98,4580.02 2734.98,4580.02 2827.96,4487.04 ; 2534.98,4580.02 2642,4473 2642,4448 ; 2642,4448 2681.04,4487.04 2827.96,4487.04 ; 3631,3581.34 3639.62,3581.34 3663,3604.72 3663,3613.34 ; 3631,3581.34 3663,3613.34
VCC-5.0: C11.2 C12.2 C15.2 C16.2 D1.1 P1.1 U3.3 U4.3 | length 2103.2
  Top Layer w7.87: D1.1 2841,6016 3014,6016 3080,5950 P1.1 ; U3.3@3620,5642 C11.2 C12.2 3744,5570 3777,5537 3777,5504 3809,5472 4109,5472 4117,5480 4117,5573.46 C16.2 C15.2 4025,5631 3995.03,5660.97 U4.3 ; U3.3@3620.03,5642.03 U3.3 v1(3620.03,5843)
  Bottom Layer w7.87: P1.1 3146,5996 3467.03,5996 v1(3620.03,5843)
VCC_180V: P2.1 P3.1 R4.2 | length 761.1
  Top Layer w7.87: P3.1 3953,3526.72 3908,3571.72 3908,3847.72 3943,3882.72 P2.1 3953.26,3882.48 P2.1@3960.57,3875.86 ; P2.1@3958,3887.72 R4.2
Y1: *1.1 U6.14 | length 241.8
  Bottom Layer w7.87: *1.1 2572,4728 2572,4715 U6.14
Y1_N: *1.2 P9.1 P10.1 P11.1 P14.1 P15.1 P16.1 | length 5794
  Top Layer w7.87: P11.1 P10.1 P9.1 4551,5378.58 4534,5361.58 4534,5080 4506.52,5052.52 4389.52,5052.52 4361,5024 v1(4361,4618) 4361,4544 4401.06,4503.94 P14.1 P15.1 P16.1
  Bottom Layer w7.87: *1.2 2606,4794 3013,4794 3042.91,4764.09 3042.91,4689.29 3074.29,4657.91 3136,4657.91 3234.43,4756.34 3660.25,4756.34 3693,4723.59 3693,4669 ; 3693,4669 3693,4618 v1(4361,4618) 4310,4669 3693,4669
Y2: *1.3 U6.13 | length 184
  Top Layer w7.87: *1.3 2630,4785 U6.13
Y2_N: *1.4 P9.2 P10.2 P11.2 P14.2 P15.2 P16.2 | length 4766.8
  Top Layer w7.87: v1(4380,4968) v1(4380,4733) 4380,4592 4418.85,4553.15 P14.2 P15.2 P16.2 ; v1(4504.94,5092.94) 4504.94,5414.94 4517.8,5427.8 P9.2 P10.2 P11.2
  Bottom Layer w7.87: *1.4 2779,4821 3057.66,4821 3058.66,4820 3058.66,4697.88 3082.88,4673.66 3120,4673.66 3218.43,4772.09 3689.91,4772.09 3705.66,4756.34 4356.66,4756.34 v1(4380,4733) ; v1(4380,4968) v1(4504.94,5092.94)
Y3: *1.5 U6.12 | length 167.4
  Top Layer w7.87: U6.12 2830,4745 *1.5
Y3_N: *1.6 P9.3 P10.3 P11.3 P14.3 P15.3 P16.3 | length 5010.8
  Top Layer w7.87: *1.6 2930,4946 v1(3036,5052) ; v1(4247,5052) 4294,5099 4457,5099 4478,5120 4478,5453.01 4502,5477.01 P9.3 P10.3 5391.99,5477.01 5415,5477.01 P11.3 ; P14.3 P15.3 P16.3 5576.36,4602.36 5636,4662 v1(5636,5233)
  Bottom Layer w7.87: v1(3036,5052) v1(4247,5052) ; v1(5435,5477.01) 5435,5434 v1(5636,5233)
Y4: *1.9 U6.11 | length 478.1
  Top Layer w7.87: U6.11 2900,4784 2887.09,4796.91 2887.09,5127.09 *1.9
Y4_N: *1.8 P9.4 P10.4 P11.4 P14.4 P15.4 P16.4 | length 4316
  Top Layer w7.87: v1(4459,5128) 4459,5473.22 4512,5526.22 P9.4 P10.4 P11.4 ; v1(4495,4762) 4495,4668.57 4512,4651.57 P14.4 P15.4 P16.4
  Bottom Layer w7.87: *1.8 3088,5112 4443,5112 ; v1(4459,5128) 4443,5112 ; v1(4495,4762) 4352,4905 4352,5021 4443,5112
Y5: *1.11 U6.10 | length 749.2
  Top Layer w7.87: *1.11 2871.34,5028.66 2871.34,4842.34 2858,4829 2858,4672 2891,4639 2924,4639 U6.10
Y5_N: *1.10 P9.5 P10.5 P11.5 P14.5 P15.5 P16.5 | length 4903.2
  Top Layer w7.87: v1(4168,5022) 4386.79,5240.79 4386.79,5485.23 4477,5575.43 P9.5 P10.5 P11.5 5483,5575.43 5492,5566.43 5492,5345 5489,5342 5489,5043 5496,5036 5496,4712.79 5484,4700.79 P16.5 P15.5 P14.5
  Bottom Layer w7.87: *1.10 2978,5022 v1(4168,5022)
Y6: *1.13 U6.9 | length 902
  Bottom Layer w7.87: *1.13 2694,5006 3054,5006 3100,4960 U6.9
Y6_N: *1.12 P9.6 P10.6 P11.6 P14.6 P15.6 P16.6 | length 5468.4
  Top Layer w7.87: v1(4154,5082) 4369.61,5297.61 4369.61,5492 4502.25,5624.65 P9.6 P10.6 P11.6 5539,5624.65 5701,5462.65 v1(5701,5194) ; P14.6 P15.6 v1(5257,4750) P16.6
  Bottom Layer w7.87: *1.12 2688,5112 2752,5112 2788,5148 2788,5200 2800,5212 2960,5212 2980,5192 2980,5106 3004,5082 v1(4154,5082) ; v1(5257,4750) v1(5701,5194)
Y7: *2.1 U6.7 | length 1031.8
  Top Layer w7.87: U6.7 3050,4365 3458,4365 3477,4384 3477,4441 3380,4538 *2.1
Y7_N: *2.2 P9.7 P10.7 P11.7 P14.7 P15.7 P16.7 | length 4901.3
  Top Layer w7.87: *2.2 3522,4912 3618,4912 3634,4896 3634,4786 3693.66,4726.34 3693.66,4692 3712,4673.66 3760,4673.66 3776.34,4690 3776.34,4732.8 3760,4749.14 3760,4821 3738.66,4842.34 3738.66,4896 3754.66,4912 3883,4912 4265,5294 4265,5504 4434.86,5673.86 P9.7 P10.7 P11.7 ; v2(4440,4770) 4456.82,4770 4486.04,4799.21 P14.7 P15.7 P16.7
  Bottom Layer w7.87: *2.2 3562.16,4787.84 3717.74,4787.84 3733.49,4772.09 4437.91,4772.09 v2(4440,4770)
Y8: *2.3 U7.14 | length 173.6
  Top Layer w7.87: U7.14 3580,4760 *2.3
Y8_N: *2.4 P9.8 P10.8 P11.8 P14.8 P15.8 P16.8 | length 4231.9
  Top Layer w7.87: *2.4 3680,5005 3825,5150 3825,5184 3857,5216 3898,5216 3930,5184 3930,5150.66 3952,5128.66 4000,5128.66 4215.96,5344.62 4215.96,5520.03 4419,5723.07 P9.8 P10.8 P11.8 ; v1(4429,4800) 4477.42,4848.42 P14.8 P15.8 P16.8
  Bottom Layer w7.87: *2.4 3750,4800 v1(4429,4800)
Y9: *2.5 U7.13 | length 388.4
  Top Layer w7.87: U7.13 3692.09,4657.91 3776,4657.91 3792.09,4674 3792.09,4772.09 3780,4784.18 *2.5
Y9_N: *2.6 P9.9 P10.9 P11.9 P14.9 P15.9 P16.9 | length 3846
  Top Layer w7.87: *2.6 4297,5287 v1(4297,5441) ; v1(4197,5525) 4444.28,5772.28 P9.9 P10.9 P11.9 ; v1(4399,4828) 4468.64,4897.64 P14.9 P15.9 P16.9
  Bottom Layer w7.87: *2.6 3922,4828 v1(4399,4828) ; v1(4197,5525) 4213,5525 v1(4297,5441)
Y10: *2.9 U7.12 | length 525.1
  Top Layer w7.87: U7.12 3735,4801.11 3722.91,4813.2 3722.91,5012.91 *2.9
Y10_N: *2.8 P9.10 P10.10 P11.10 P14.10 P15.10 P16.10 | length 3650.9
  Top Layer w7.87: *2.8 4148.5,5338.5 4148.5,5531.99 4438,5821.5 P9.10 P10.10 P11.10 ; P14.10 v1(4690.15,4946.85) P15.10 P16.10
  Bottom Layer w7.87: *2.8 4443.31,5170 ; v1(4690.15,4946.85) 4524,5113 ; 4443.31,5170 4467,5170 4524,5113 ; 4443.31,5170 4500.31,5113 4524,5113
pads on no net: *2.10 *2.12 P4.0 P7.0 P9.0 P10.0 P11.0 P14.0 P15.0 P16.0 U1.2 U1.38 U5.12 U5.13 U5.14 U5.15 U5.16 U5.17 U6.15 U7.7 U7.9 U7.10 U7.11 U7.15 Y1.

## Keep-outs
Keep-Out Layer:
  lines w7: 5345,2950 5345,4275 5847.64,4275
  lines w10: 5345,2950 2050,2950 2050,6099.61 5847.64,6099.61 5847.64,4275

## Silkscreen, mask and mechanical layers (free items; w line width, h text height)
Top Overlay:
  text "3.3" at 4570,6070 h80 r180
  text "+" at 4105,6050 h80 r180
  text "+" at 2940,5880 h80 r270
  text "5v" at 3245,5830 h80 r270
  text "RST" at 2150,5300 h80 r270
  text "+" at 4030,4040 h80 r270
  text "+" at 2270,3960 h80
  text "180v" at 3945,3650 h80 r270
  text "3.3" at 2260,3645 h80 r270
  text "-" at 2220,3630 h80 r90
  text "+" at 2170,3525 h80
  text "+" at 4030,3520 h80 r270
  text "-" at 2220,3165 h80 r90
Drill Drawing:
  text ".LEGEND" at 6097.64,3200 h60
  text "Drill Drawing." at 6097.64,3100 h60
